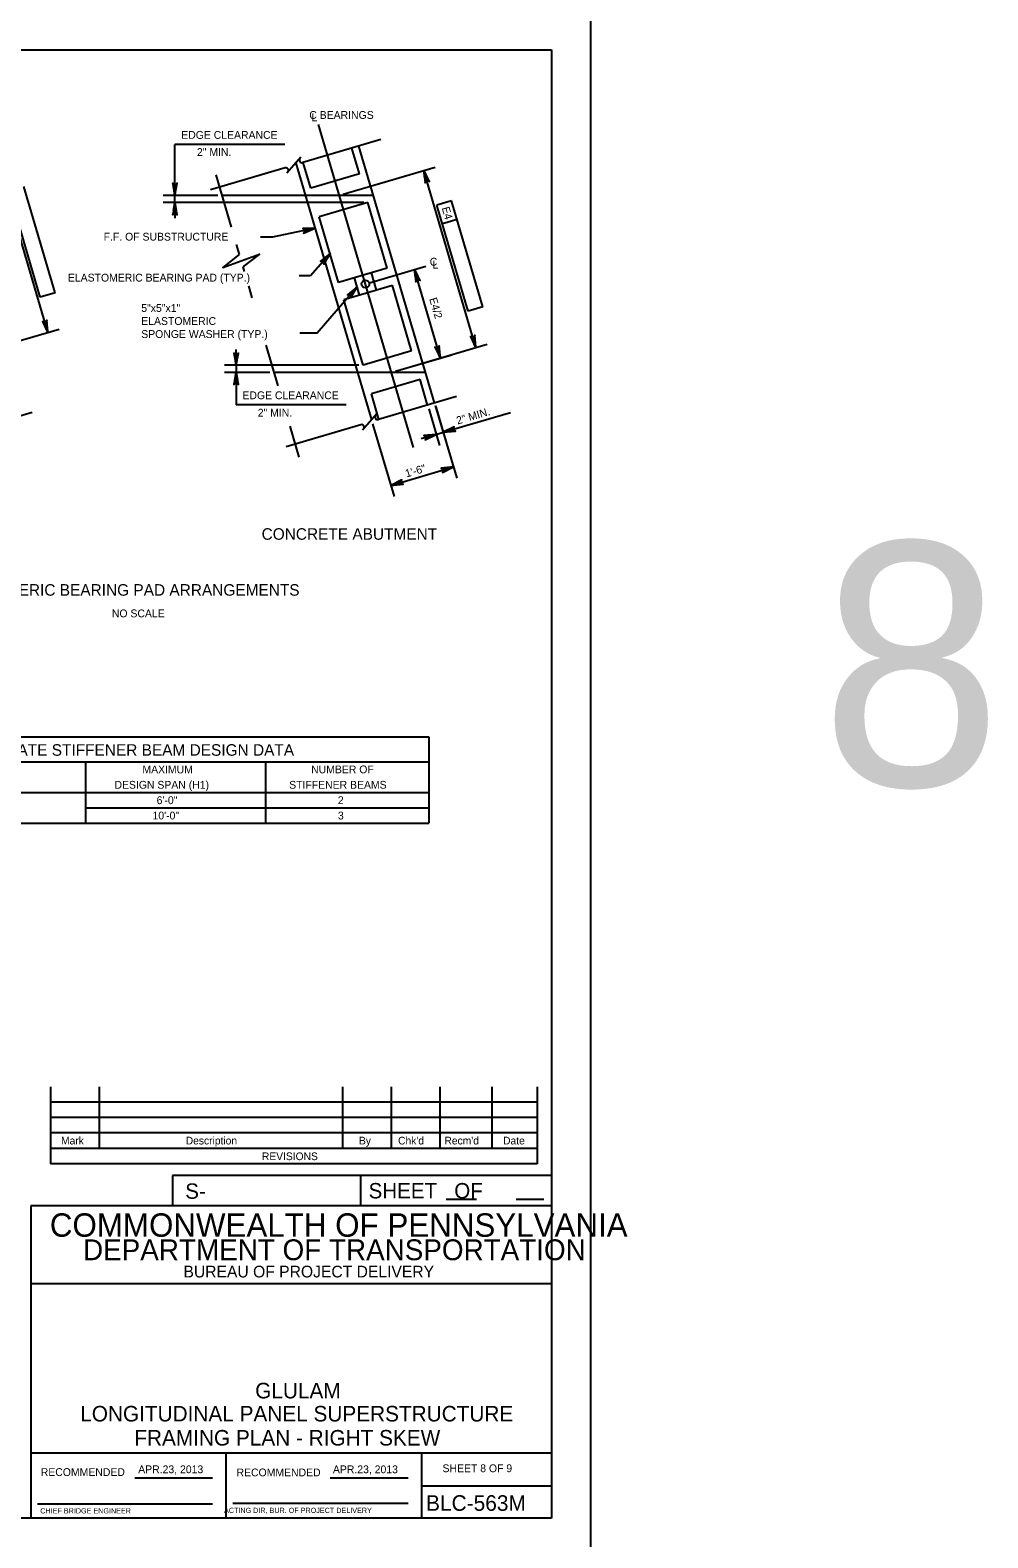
# Model space of a CAD drawing. Extents: x 638268 to 640277, y 295465 to 298435.
# Drawn here: x 639902 to 640270, y 296661 to 297240 of the extents above; entities that cross this region are included whole.
import ezdxf

# ---------------------------------------------------------------- set-up
doc = ezdxf.new("R2010")
doc.units = 0
for name, color, linetype in [('1', 7, 'Continuous'), ('2', 7, 'Continuous'), ('3', 7, 'Continuous'), ('4', 7, 'Continuous'), ('53', 7, 'Continuous'), ('7', 7, 'Continuous'), ('8', 7, 'Continuous'), ('PLT-BNDY', 7, 'Continuous')]:
    doc.layers.add(name, color=color, linetype=linetype)

msp = doc.modelspace()

# ---------------------------------------------------------------- linework, layer by layer
at = {"layer": '2'}
for p, q in [((639316.46, 297232.46), (640102.46, 297232.46)), ((640102.46, 297232.46), (640102.46, 296668.46)), ((639909.92, 296834.15), (639909.92, 296804.62)), ((639928.62, 296834.15), (639928.62, 296810.53)), ((640022.13, 296834.15), (640022.13, 296810.53)), ((640040.83, 296834.15), (640040.83, 296810.53)), ((640059.53, 296834.15), (640059.53, 296810.53)), ((640079.59, 296834.15), (640079.59, 296810.53)), ((640096.94, 296834.15), (640096.94, 296804.62)), ((640096.94, 296828.24), (639909.92, 296828.24)), ((640096.94, 296822.34), (639909.92, 296822.34)), ((640096.94, 296816.43), (639909.92, 296816.43)), ((640096.94, 296810.53), (639909.92, 296810.53)), ((640096.94, 296804.62), (639909.92, 296804.62)), ((640102.46, 296800.11), (639956.78, 296800.11)), ((639956.78, 296800.11), (639956.78, 296788.46)), ((640029.09, 296800.11), (640029.09, 296788.46)), ((640102.46, 296800.11), (640102.46, 296788.46)), ((640061.95, 296791), (640073.6, 296791)), ((640088.83, 296791), (640099.56, 296791)), ((640102.46, 296788.46), (639902.46, 296788.46)), ((639902.46, 296788.46), (639902.46, 296668.46)), ((640102.46, 296788.46), (639956.78, 296788.46)), ((640102.46, 296758.46), (639902.46, 296758.46)), ((640102.46, 296693.46), (639902.46, 296693.46)), ((639977.46, 296668.46), (639977.46, 296693.46)), ((640052.46, 296693.46), (640052.46, 296668.46)), ((639942.42, 296683.96), (639972.19, 296683.96)), ((640017.42, 296683.96), (640047.33, 296683.96)), ((640052.46, 296680.96), (640102.46, 296680.96)), ((639904.96, 296673.96), (639972.19, 296673.96)), ((639980.08, 296674.33), (640047.33, 296674.33)), ((640102.46, 296668.46), (639316.46, 296668.46))]:
    msp.add_line(p, q, dxfattribs=at)
at = {"layer": '3'}
for p, q in [((640036.9, 297197.91), (640006.89, 297189.07)), ((640057.54, 297096.78), (640028.48, 297195.43)), ((639908.99, 297123.91), (639888.97, 297191.89)), ((640006.2, 297191.13), (640000.78, 297185)), ((640000.18, 297187.09), (639971.5, 297178.64)), ((639973.45, 297184.44), (639979.38, 297164.3)), ((640004.24, 297188.91), (640033.29, 297090.26)), ((640028.71, 297184.74), (640010.01, 297179.24)), ((640034.07, 297176.48), (639975.79, 297176.48)), ((640031.95, 297173.73), (640013.26, 297168.22)), ((639981.36, 297157.59), (639982.47, 297153.8)), ((639983.89, 297149), (639984.41, 297147.23)), ((640039.37, 297148.55), (640020.67, 297143.05)), ((639986.02, 297141.76), (639987.36, 297137.21)), ((640041.31, 297141.94), (640022.62, 297136.43)), ((639856.03, 297108.31), (639913.31, 297125.18)), ((639992.73, 297118.98), (639997.32, 297103.39)), ((640048.73, 297116.77), (640030.04, 297111.26)), ((640054.09, 297108.5), (639995.82, 297108.5)), ((640051.98, 297105.75), (640033.28, 297100.24)), ((640065.96, 297099.26), (640035.95, 297090.42)), ((640035.25, 297092.48), (640029.84, 297086.35)), ((640029.24, 297088.44), (640000.56, 297080)), ((640001.88, 297087.92), (640005.41, 297075.93))]:
    msp.add_line(p, q, dxfattribs=at)
msp.add_lwpolyline([(639908.63, 297126.93), (639907.66, 297126.65), (639908.99, 297123.91)], close=True, dxfattribs=at)
for centre, start, end in [((640006.6, 297190.05), 136.41201, 286.41201), ((640000.38, 297186.09), 318.54477, 101.08342), ((640035.66, 297091.4), 136.41201, 286.41201), ((640029.44, 297087.44), 318.54477, 101.08342)]:
    msp.add_arc(centre, 1.02, start, end, dxfattribs=at)
at = {"layer": '4'}
for p, q in [((640049.49, 297079.7), (640012.94, 297203.78)), ((640000.05, 297196.02), (639957.79, 297196.02)), ((639957.79, 297179.48), (639957.79, 297196.02)), ((640022.48, 297176.92), (640057.73, 297187.31)), ((640073.44, 297118.06), (640053.42, 297186.04)), ((639906.04, 297137.45), (639894.03, 297178.24)), ((639911.7, 297139.12), (639899.69, 297179.91)), ((639974.23, 297176.48), (639953.29, 297176.48)), ((640030.39, 297173.73), (639953.29, 297173.73)), ((639957.79, 297173.73), (639957.79, 297176.48)), ((640064.09, 297174.45), (640058.43, 297172.78)), ((640064.09, 297174.45), (640058.43, 297172.78)), ((640070.44, 297131.99), (640058.43, 297172.78)), ((640076.11, 297133.66), (640064.09, 297174.45)), ((639957.79, 297170.73), (639957.79, 297167.73)), ((640066.23, 297167.19), (640060.57, 297165.52)), ((639995.23, 297160.42), (639990.67, 297160.42)), ((640032.49, 297142.93), (640054.12, 297149.3)), ((640009.89, 297145.57), (640005.53, 297145.57)), ((640059.81, 297114.04), (640049.8, 297148.03)), ((639911.7, 297139.12), (639906.04, 297137.45)), ((640076.11, 297133.66), (640070.44, 297131.99)), ((640012.42, 297123.56), (640005.8, 297123.56)), ((639981.31, 297114.26), (639981.31, 297117.26)), ((640042.5, 297108.95), (640077.76, 297119.33)), ((640042.5, 297108.95), (640064.13, 297115.31)), ((640028.47, 297111.26), (639976.81, 297111.26)), ((639994.25, 297108.5), (639976.81, 297108.5)), ((639981.31, 297111.26), (639981.31, 297108.5)), ((639981.31, 297105.5), (639981.31, 297096.04)), ((639874.38, 297084.88), (639902.9, 297093.29)), ((640023.58, 297096.04), (639981.31, 297096.04)), ((640055.29, 297094.49), (640059.44, 297080.41)), ((640057.81, 297095.86), (640066.04, 297067.91)), ((640057.98, 297095.28), (640062.13, 297081.21)), ((640060.86, 297085.52), (640086.77, 297093.15)), ((640033.74, 297088.77), (640041.97, 297060.82)), ((640058.17, 297084.73), (640060.86, 297085.52)), ((640058.17, 297084.73), (640052.41, 297083.03)), ((640040.7, 297065.14), (640064.77, 297072.23))]:
    msp.add_line(p, q, dxfattribs=at)
for points in [[(640054.75, 297183.3), (640053.79, 297183.02), (640053.42, 297186.04)], [(639958.29, 297179.48), (639957.29, 297179.48), (639957.79, 297176.48)], [(639958.29, 297170.73), (639957.29, 297170.73), (639957.79, 297173.73)], [(640011.62, 297163.87), (640008.73, 297163), (640008.63, 297163.49)], [(640017.39, 297154.18), (640015.61, 297151.76), (640015.23, 297152.08)], [(640051.13, 297145.3), (640050.17, 297145.01), (640049.8, 297148.03)], [(640027.75, 297141.32), (640025.98, 297138.88), (640025.6, 297139.21)], [(640073.07, 297121.08), (640072.11, 297120.79), (640073.44, 297118.06)], [(639981.81, 297114.26), (639980.81, 297114.26), (639981.31, 297111.26)], [(640059.44, 297117.06), (640058.48, 297116.78), (640059.81, 297114.04)], [(639981.81, 297105.5), (639980.81, 297105.5), (639981.31, 297108.5)], [(640063.59, 297086.85), (640063.88, 297085.89), (640060.86, 297085.52)], [(640055.15, 297084.36), (640055.43, 297083.4), (640058.17, 297084.73)], [(640061.75, 297071.86), (640062.04, 297070.9), (640064.77, 297072.23)], [(640043.43, 297066.47), (640043.72, 297065.51), (640040.7, 297065.14)]]:
    msp.add_lwpolyline(points, close=True, dxfattribs=at)
for points in [[(640053.42, 297186.04), (640053.9, 297181.32), (640054.03, 297181.74), (640054.28, 297182), (640054.57, 297182.14), (640054.88, 297182.18), (640055.23, 297182.09), (640055.57, 297181.81), (640053.42, 297186.04), (640055.23, 297182.09), (640054.88, 297182.18), (640053.42, 297186.04), (640054.57, 297182.14), (640054.28, 297182), (640053.42, 297186.04), (640054.03, 297181.74)], [(639957.79, 297176.48), (639958.66, 297181.14), (639958.41, 297180.79), (639958.1, 297180.6), (639957.79, 297180.55), (639957.47, 297180.6), (639957.16, 297180.79), (639956.91, 297181.14), (639957.79, 297176.48), (639957.16, 297180.79), (639957.47, 297180.6), (639957.79, 297176.48), (639957.79, 297180.55), (639958.1, 297180.6), (639957.79, 297176.48), (639958.41, 297180.79)], [(639957.79, 297173.73), (639956.91, 297169.07), (639957.16, 297169.42), (639957.47, 297169.61), (639957.79, 297169.66), (639958.1, 297169.61), (639958.41, 297169.42), (639958.66, 297169.07), (639957.79, 297173.73), (639958.41, 297169.42), (639958.1, 297169.61), (639957.79, 297173.73), (639957.79, 297169.66), (639957.47, 297169.61), (639957.79, 297173.73), (639957.16, 297169.42)], [(640011.62, 297163.87), (639995.23, 297160.42)], [(640011.62, 297163.87), (640006.88, 297163.76), (640007.28, 297163.59), (640007.52, 297163.32), (640007.64, 297163.03), (640007.65, 297162.71), (640007.54, 297162.37), (640007.23, 297162.05), (640011.62, 297163.87), (640007.54, 297162.37), (640007.65, 297162.71), (640011.62, 297163.87), (640007.64, 297163.03), (640007.52, 297163.32), (640011.62, 297163.87), (640007.28, 297163.59)], [(639982.47, 297153.8), (639976.14, 297148.76), (639990.27, 297153.87), (639983.89, 297149)], [(640017.39, 297154.18), (640009.89, 297145.57)], [(640017.39, 297154.18), (640013.67, 297151.24), (640014.1, 297151.35), (640014.45, 297151.29), (640014.72, 297151.12), (640014.92, 297150.87), (640015.04, 297150.53), (640014.99, 297150.09), (640017.39, 297154.18), (640015.04, 297150.53), (640014.92, 297150.87), (640017.39, 297154.18), (640014.72, 297151.12), (640014.45, 297151.29), (640017.39, 297154.18), (640014.1, 297151.35)], [(640049.8, 297148.03), (640050.28, 297143.32), (640050.42, 297143.73), (640050.66, 297144), (640050.95, 297144.13), (640051.26, 297144.17), (640051.62, 297144.08), (640051.95, 297143.81), (640049.8, 297148.03), (640051.62, 297144.08), (640051.26, 297144.17), (640049.8, 297148.03), (640050.95, 297144.13), (640050.66, 297144), (640049.8, 297148.03), (640050.42, 297143.73)], [(640027.75, 297141.32), (640012.42, 297123.56)], [(640027.75, 297141.32), (640024.04, 297138.36), (640024.47, 297138.47), (640024.82, 297138.4), (640025.09, 297138.24), (640025.3, 297138), (640025.41, 297137.65), (640025.37, 297137.22), (640027.75, 297141.32), (640025.41, 297137.65), (640025.3, 297138), (640027.75, 297141.32), (640025.09, 297138.24), (640024.82, 297138.4), (640027.75, 297141.32), (640024.47, 297138.47)], [(639908.99, 297123.91), (639908.51, 297128.63), (639908.38, 297128.21), (639908.13, 297127.95), (639907.84, 297127.81), (639907.53, 297127.77), (639907.18, 297127.86), (639906.84, 297128.13), (639908.99, 297123.91), (639907.18, 297127.86), (639907.53, 297127.77), (639908.99, 297123.91), (639907.84, 297127.81), (639908.13, 297127.95), (639908.99, 297123.91), (639908.38, 297128.21)], [(640073.44, 297118.06), (640072.96, 297122.77), (640072.82, 297122.36), (640072.58, 297122.1), (640072.29, 297121.96), (640071.98, 297121.92), (640071.63, 297122.01), (640071.29, 297122.28), (640073.44, 297118.06), (640071.63, 297122.01), (640071.98, 297121.92), (640073.44, 297118.06), (640072.29, 297121.96), (640072.58, 297122.1), (640073.44, 297118.06), (640072.82, 297122.36)], [(639981.31, 297111.26), (639982.18, 297115.92), (639981.94, 297115.56), (639981.62, 297115.38), (639981.31, 297115.32), (639981, 297115.38), (639980.69, 297115.56), (639980.44, 297115.92), (639981.31, 297111.26), (639980.69, 297115.56), (639981, 297115.38), (639981.31, 297111.26), (639981.31, 297115.32), (639981.62, 297115.38), (639981.31, 297111.26), (639981.94, 297115.56)], [(640059.81, 297114.04), (640059.33, 297118.76), (640059.2, 297118.35), (640058.95, 297118.08), (640058.67, 297117.94), (640058.35, 297117.9), (640058, 297117.99), (640057.66, 297118.27), (640059.81, 297114.04), (640058, 297117.99), (640058.35, 297117.9), (640059.81, 297114.04), (640058.67, 297117.94), (640058.95, 297118.08), (640059.81, 297114.04), (640059.2, 297118.35)], [(639981.31, 297108.5), (639980.44, 297103.84), (639980.69, 297104.2), (639981, 297104.39), (639981.31, 297104.44), (639981.62, 297104.39), (639981.94, 297104.2), (639982.18, 297103.84), (639981.31, 297108.5), (639981.94, 297104.2), (639981.62, 297104.39), (639981.31, 297108.5), (639981.31, 297104.44), (639981, 297104.39), (639981.31, 297108.5), (639980.69, 297104.2)], [(640060.86, 297085.52), (640065.57, 297086), (640065.16, 297086.14), (640064.89, 297086.38), (640064.75, 297086.67), (640064.72, 297086.98), (640064.81, 297087.33), (640065.08, 297087.68), (640060.86, 297085.52), (640064.81, 297087.33), (640064.72, 297086.98), (640060.86, 297085.52), (640064.75, 297086.67), (640064.89, 297086.38), (640060.86, 297085.52), (640065.16, 297086.14)], [(640058.17, 297084.73), (640053.45, 297084.25), (640053.87, 297084.11), (640054.13, 297083.87), (640054.27, 297083.58), (640054.31, 297083.27), (640054.22, 297082.91), (640053.94, 297082.57), (640058.17, 297084.73), (640054.22, 297082.91), (640054.31, 297083.27), (640058.17, 297084.73), (640054.27, 297083.58), (640054.13, 297083.87), (640058.17, 297084.73), (640053.87, 297084.11)], [(640064.77, 297072.23), (640060.05, 297071.75), (640060.47, 297071.61), (640060.73, 297071.37), (640060.87, 297071.08), (640060.91, 297070.77), (640060.82, 297070.42), (640060.55, 297070.08), (640064.77, 297072.23), (640060.82, 297070.42), (640060.91, 297070.77), (640064.77, 297072.23), (640060.87, 297071.08), (640060.73, 297071.37), (640064.77, 297072.23), (640060.47, 297071.61)], [(640040.7, 297065.14), (640045.41, 297065.62), (640045, 297065.76), (640044.73, 297066), (640044.59, 297066.29), (640044.56, 297066.6), (640044.65, 297066.95), (640044.92, 297067.29), (640040.7, 297065.14), (640044.65, 297066.95), (640044.56, 297066.6), (640040.7, 297065.14), (640044.59, 297066.29), (640044.73, 297066), (640040.7, 297065.14), (640045, 297065.76)]]:
    msp.add_lwpolyline(points, dxfattribs=at)
at = {"layer": '7'}
for p, q in [((640010.01, 297179.24), (640007.1, 297189.13)), ((640028.71, 297184.74), (640025.79, 297194.64)), ((640039.37, 297148.55), (640031.95, 297173.73)), ((640020.67, 297143.05), (640013.26, 297168.22)), ((640028.66, 297138.21), (640026.72, 297144.82)), ((640035.27, 297140.16), (640033.33, 297146.77)), ((640048.73, 297116.77), (640041.31, 297141.94)), ((640030.04, 297111.26), (640022.62, 297136.43)), ((640054.85, 297095.99), (640051.98, 297105.75)), ((640036.15, 297090.48), (640033.28, 297100.24))]:
    msp.add_line(p, q, dxfattribs=at)
msp.add_circle((640030.99, 297142.49), 1.48, dxfattribs=at)
at = {"layer": '8'}
for p, q in [((639833.15, 296968.52), (640055.35, 296968.52)), ((640055.35, 296968.52), (640055.35, 296935.36)), ((639833.15, 296958.99), (640055.35, 296958.99)), ((639923.36, 296958.99), (639923.36, 296935.36)), ((639992.58, 296958.99), (639992.58, 296935.36)), ((639833.15, 296947.17), (640055.35, 296947.17)), ((639923.36, 296941.27), (640055.35, 296941.27)), ((639833.15, 296935.36), (640055.35, 296935.36))]:
    msp.add_line(p, q, dxfattribs=at)
at = {"layer": 'PLT-BNDY'}
msp.add_lwpolyline([(639276.46, 297247.46), (640117.46, 297247.46), (640117.46, 296653.46), (639276.46, 296653.46)], close=True, dxfattribs=at)

# ---------------------------------------------------------------- texts
at = {"layer": '1'}
msp.add_text('SHEET 8 OF 9', height=3, dxfattribs=at).set_placement((640060.59, 296686.17))
at = {"layer": '2'}
for s, height, p in [('Mark', 2.952, (639914.02, 296812.03)), ('Description', 2.9523, (639961.92, 296812.03)), ('By', 2.952, (640028.49, 296812.03)), ("Chk'd", 2.952, (640043.52, 296812.03)), ("Recm'd", 2.953, (640061.33, 296812.03)), ('Date', 2.952, (640083.86, 296812.03)), ('REVISIONS', 2.952, (639991.2, 296806.01)), ('S-', 5.905, (639961.73, 296791.17)), ('COMMONWEALTH OF PENNSYLVANIA', 9, (639909.71, 296776.58)), ('DEPARTMENT OF TRANSPORTATION', 8.0002, (639922.46, 296767.58)), ('BUREAU OF PROJECT DELIVERY', 4.5, (639961.05, 296760.96)), ('APR.23, 2013', 3, (639943.67, 296685.77)), ('APR.23, 2013', 3, (640018.48, 296685.77)), ('BLC-563M', 6, (640054.27, 296671.33)), ('CHIEF BRIDGE ENGINEER', 2.0002, (639906.05, 296670.33)), ('  ACTING DIR, BUR. OF PROJECT DELIVERY', 2.0002, (639975.11, 296670.51))]:
    msp.add_text(s, height=height, dxfattribs=at).set_placement(p)
for s, height, p in [('SHEET   OF', 5.907, (640032.18, 296791.31)), ('RECOMMENDED', 3, (639906.23, 296684.71)), ('RECOMMENDED', 3, (639981.44, 296684.58))]:
    msp.add_text(s, height=height, rotation=360, dxfattribs=at).set_placement(p)
at = {"layer": '3'}
for s, p in [('CONCRETE ABUTMENT', (639991.08, 297044.25)), ('ELASTOMERIC BEARING PAD ARRANGEMENTS', (639869.42, 297022.77))]:
    msp.add_text(s, height=4.4292, dxfattribs=at).set_placement(p)
at = {"layer": '4'}
for s, height, p in [('C BEARINGS', 3, (640009.4, 297205.88)), ('L', 3, (640010.3, 297204.97)), ('EDGE CLEARANCE', 3, (639960.2, 297198.22)), ('2" MIN.', 3, (639966.24, 297191.64)), ('F.F. OF SUBSTRUCTURE', 3, (639930.39, 297159.14)), ('C', 3, (640055.67, 297149.53)), ('L', 3, (640056.77, 297148.41)), ('ELASTOMERIC BEARING PAD (TYP.)', 3, (639916.65, 297143.41)), ('5"x5"x1"', 3, (639944.84, 297131.75)), ('ELASTOMERIC', 3, (639944.84, 297126.75)), ('SPONGE WASHER (TYP.)', 3, (639944.84, 297121.75)), ('EDGE CLEARANCE', 3, (639983.72, 297098.23)), ('2" MIN.', 3, (639989.59, 297091.54)), ('NO SCALE', 3, (639933.55, 297014.47)), ('TABLE 1 - INTERMEDIATE STIFFENER BEAM DESIGN DATA', 4.4292, (639835.73, 296961.31)), ('MAXIMUM', 3, (639945.29, 296954.55)), ('NUMBER OF ', 3, (640010.11, 296954.56)), ('DESIGN SPAN (H1)', 3, (639934.55, 296948.65)), ('STIFFENER BEAMS', 3, (640001.67, 296948.65)), ('6\'-0"', 3, (639950.74, 296942.74)), ('2', 3, (640020.38, 296942.75)), ('10\'-0"', 3, (639949.16, 296936.84)), ('3', 3, (640020.4, 296936.84)), ('GLULAM', 5.971, (639988.62, 296714.51)), ('LONGITUDINAL PANEL SUPERSTRUCTURE', 5.9714, (639921.39, 296705.65)), ('FRAMING PLAN - RIGHT SKEW', 5.9714, (639942.17, 296696.4))]:
    msp.add_text(s, height=height, dxfattribs=at).set_placement(p)
for s, rotation, p in [('E4', 286.47379, (640060.27, 297171.65)), ('E4/2', 286.41201, (640055.45, 297136.76)), ('2" MIN.', 16.41628, (640066.41, 297088.49)), ('1\'-6"', 16.41628, (640046.76, 297068.15))]:
    msp.add_text(s, height=3, rotation=rotation, dxfattribs=at).set_placement(p)
at = {"layer": '53'}
msp.add_text('8', height=93.75, dxfattribs=at).set_placement((640205.86, 296949.64))

doc.saveas('drawing.dxf')
